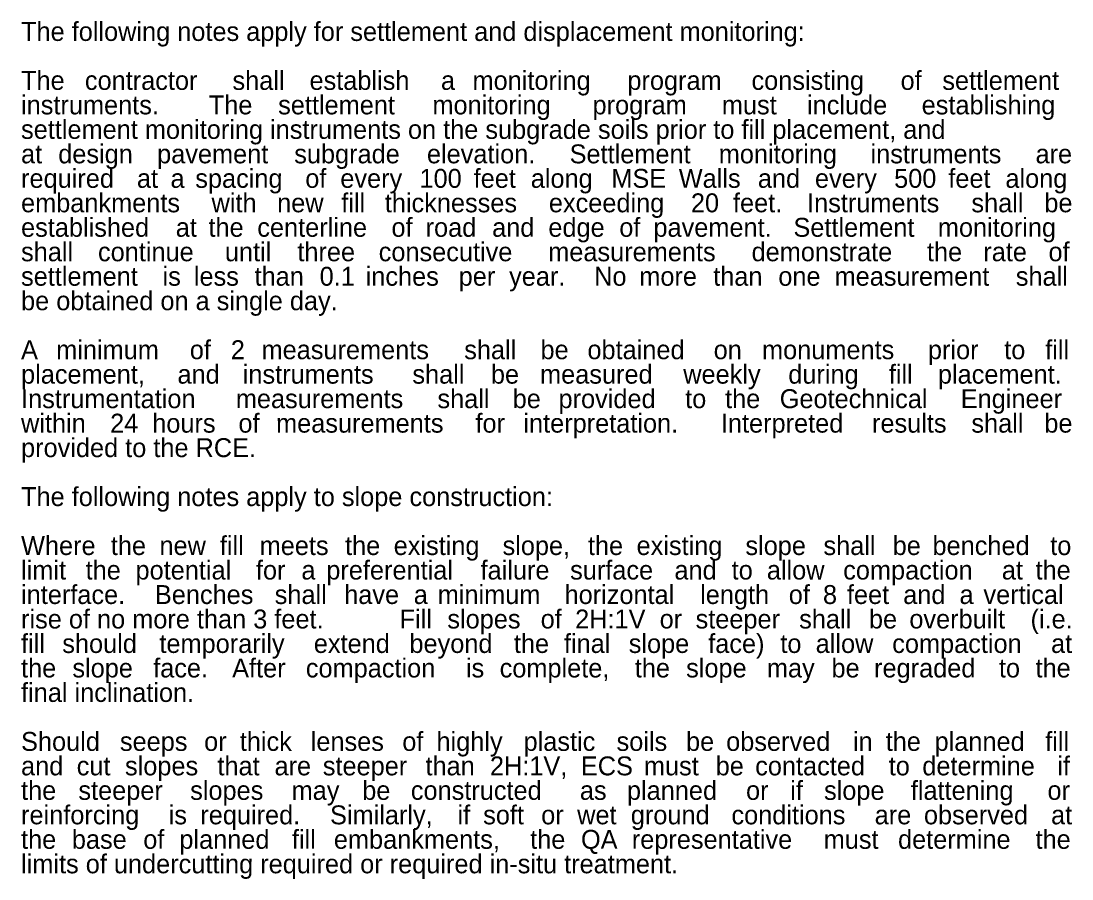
# Model space of a CAD drawing. Extents: x 4804 to 5434, y 4929 to 5221.
# Drawn here: x 5186.9 to 5263.8, y 5038.5 to 5101.3 of the extents above; entities that cross this region are included whole.
import ezdxf

# ---------------------------------------------------------------- set-up
doc = ezdxf.new("R2010")
doc.units = 0
doc.layers.add('RD_TX_RoadID', color=7, linetype='Continuous')

msp = doc.modelspace()

# ---------------------------------------------------------------- texts
at = {"layer": 'RD_TX_RoadID'}
for s, p in [('The following notes apply for settlement and displacement monitoring:', (5186.949, 5099.812)), ('The ', (5186.949, 5096.229)), ('contractor ', (5191.618, 5096.229)), ('shall ', (5202.412, 5096.229)), ('establish ', (5208.048, 5096.229)), ('a ', (5217.661, 5096.229)), ('monitoring ', (5219.967, 5096.229)), ('program ', (5231.297, 5096.229)), ('consisting ', (5240.372, 5096.229)), ('of ', (5251.274, 5096.229)), ('settlement ', (5254.329, 5096.229)), ('instruments. ', (5186.949, 5094.437)), (' The ', (5200.166, 5094.437)), ('settlement ', (5205.753, 5094.437)), ('monitoring ', (5217.036, 5094.437)), ('program ', (5228.747, 5094.437)), ('must ', (5238.203, 5094.437)), ('include ', (5244.435, 5094.437)), ('establishing ', (5252.817, 5094.437)), ('settlement monitoring instruments on the subgrade soils prior to fill placement, and ', (5186.949, 5092.645)), ('at ', (5186.949, 5090.853)), ('design ', (5189.668, 5090.853)), ('pavement ', (5196.901, 5090.853)), ('subgrade ', (5206.929, 5090.853)), ('elevation. ', (5216.635, 5090.853)), (' Settlement ', (5226.555, 5090.853)), ('monitoring ', (5237.978, 5090.853)), ('instruments ', (5249.078, 5090.853)), ('are ', (5261.146, 5090.853)), ('required ', (5186.949, 5089.061)), ('at ', (5195.424, 5089.061)), ('a ', (5197.88, 5089.061)), ('spacing ', (5199.692, 5089.061)), ('of ', (5207.737, 5089.061)), ('every ', (5210.3, 5089.061)), ('100 ', (5216.09, 5089.061)), ('feet ', (5220.053, 5089.061)), ('along ', (5224.228, 5089.061)), ('MSE ', (5230.123, 5089.061)), ('Walls ', (5235.052, 5089.061)), ('and ', (5240.839, 5089.061)), ('every ', (5245.015, 5089.061)), ('500 ', (5250.805, 5089.061)), ('feet ', (5254.768, 5089.061)), ('along ', (5258.943, 5089.061)), ('embankments ', (5186.949, 5087.27)), ('with ', (5200.883, 5087.27)), ('fill ', (5210.369, 5087.27)), ('thicknesses ', (5213.553, 5087.27)), ('exceeding ', (5225.553, 5087.27)), ('20 ', (5235.941, 5087.27)), ('feet. ', (5239.019, 5087.27)), (' Instruments ', (5243.923, 5087.27)), ('shall ', (5256.457, 5087.27)), ('be ', (5261.792, 5087.27)), ('new ', (5205.679, 5087.27)), ('established ', (5186.949, 5085.478)), ('at ', (5198.263, 5085.478)), ('the ', (5200.655, 5085.478)), ('centerline ', (5204.229, 5085.478)), ('of ', (5214.038, 5085.478)), ('road ', (5216.537, 5085.478)), ('and ', (5221.402, 5085.478)), ('edge ', (5225.515, 5085.478)), ('of ', (5230.703, 5085.478)), ('pavement. ', (5233.202, 5085.478)), ('Settlement ', (5243.441, 5085.478)), ('monitoring ', (5254.001, 5085.478)), ('shall ', (5186.949, 5083.686)), ('continue ', (5192.576, 5083.686)), ('until ', (5201.856, 5083.686)), ('three ', (5207.158, 5083.686)), ('consecutive ', (5213.107, 5083.686)), ('measurements ', (5225.506, 5083.686)), ('demonstrate ', (5240.378, 5083.686)), ('the ', (5253.205, 5083.686)), ('rate ', (5257.327, 5083.686)), ('of ', (5262.094, 5083.686)), ('settlement ', (5186.949, 5081.894)), ('is ', (5197.298, 5081.894)), ('less ', (5199.587, 5081.894)), ('than ', (5204.027, 5081.894)), ('0.1 ', (5208.787, 5081.894)), ('inches ', (5212.152, 5081.894)), ('  No ', (5227.835, 5081.894)), ('than ', (5237.573, 5081.894)), ('measurement ', (5246.449, 5081.894)), ('shall ', (5259.703, 5081.894)), ('per ', (5218.956, 5081.894)), ('year. ', (5222.643, 5081.894)), ('more ', (5232.166, 5081.894)), ('one ', (5242.333, 5081.894)), ('be obtained on a single day.  ', (5186.949, 5080.102)), ('A ', (5186.949, 5076.519)), ('minimum ', (5189.519, 5076.519)), ('of ', (5199.291, 5076.519)), ('2 ', (5202.289, 5076.519)), ('measurements ', (5204.538, 5076.519)), ('shall ', (5219.363, 5076.519)), ('be ', (5224.942, 5076.519)), ('obtained ', (5228.373, 5076.519)), ('monuments ', (5241.142, 5076.519)), ('prior ', (5253.277, 5076.519)), ('to ', (5258.856, 5076.519)), ('fill ', (5261.854, 5076.519)), ('on ', (5237.605, 5076.519)), ('placement, ', (5186.949, 5074.727)), ('and ', (5198.389, 5074.727)), ('instruments ', (5203.165, 5074.727)), ('shall ', (5215.57, 5074.727)), ('be ', (5221.314, 5074.727)), ('measured ', (5224.908, 5074.727)), ('weekly ', (5235.382, 5074.727)), ('during ', (5243.062, 5074.727)), ('fill ', (5250.416, 5074.727)), ('placement. ', (5254.007, 5074.727)), ('Instrumentation ', (5186.949, 5072.935)), ('measurements ', (5202.657, 5072.935)), ('shall ', (5217.404, 5072.935)), ('be ', (5222.906, 5072.935)), ('provided ', (5226.258, 5072.935)), ('to ', (5235.521, 5072.935)), ('the ', (5238.441, 5072.935)), ('Geotechnical ', (5242.437, 5072.935)), ('Engineer ', (5255.677, 5072.935)), ('within ', (5186.949, 5071.143)), ('24 ', (5193.465, 5071.143)), ('hours ', (5196.544, 5071.143)), ('of ', (5202.847, 5071.143)), ('measurements ', (5205.601, 5071.143)), ('for ', (5220.182, 5071.143)), ('interpretation. ', (5223.689, 5071.143)), (' Interpreted ', (5237.619, 5071.143)), ('results ', (5249.186, 5071.143)), ('shall ', (5256.456, 5071.143)), ('be ', (5261.792, 5071.143)), ('provided to the RCE.  ', (5186.949, 5069.351)), ('The following notes apply to slope construction:', (5186.949, 5065.768)), ('Where ', (5186.949, 5062.184)), ('the ', (5193.515, 5062.184)), ('new ', (5197.072, 5062.184)), ('fill ', (5201.489, 5062.184)), ('meets ', (5204.4, 5062.184)), ('the ', (5210.645, 5062.184)), ('existing ', (5214.202, 5062.184)), ('slope, ', (5222.165, 5062.184)), ('the ', (5228.409, 5062.184)), ('existing ', (5231.966, 5062.184)), ('slope ', (5239.929, 5062.184)), ('shall ', (5245.636, 5062.184)), ('be ', (5250.699, 5062.184)), ('benched ', (5253.611, 5062.184)), ('to ', (5262.221, 5062.184)), ('limit ', (5186.949, 5060.392)), ('the ', (5191.672, 5060.392)), ('potential ', (5195.321, 5060.392)), ('for ', (5204.127, 5060.392)), ('preferential ', (5209.276, 5060.392)), ('failure ', (5220.556, 5060.392)), ('surface ', (5227.107, 5060.392)), ('and ', (5234.734, 5060.392)), ('to ', (5238.921, 5060.392)), ('allow ', (5241.495, 5060.392)), ('compaction ', (5247.079, 5060.392)), ('at ', (5258.681, 5060.392)), ('the ', (5261.148, 5060.392)), ('a ', (5207.453, 5060.392)), ('interface. ', (5186.949, 5058.6)), (' Benches ', (5196.224, 5058.6)), ('shall ', (5205.501, 5058.6)), ('have ', (5210.585, 5058.6)), ('a ', (5215.67, 5058.6)), ('minimum ', (5217.423, 5058.6)), ('horizontal ', (5226.699, 5058.6)), ('length ', (5236.617, 5058.6)), ('of ', (5243.097, 5058.6)), ('8 ', (5245.6, 5058.6)), ('feet ', (5247.353, 5058.6)), ('and ', (5251.468, 5058.6)), ('a ', (5255.585, 5058.6)), ('vertical ', (5257.338, 5058.6)), ('rise of no more than 3 feet.', (5186.949, 5056.809)), ('Fill ', (5214.639, 5056.809)), ('slopes ', (5218.129, 5056.809)), ('of ', (5224.952, 5056.809)), ('2H:1V ', (5227.474, 5056.809)), ('or ', (5233.653, 5056.809)), ('steeper ', (5236.284, 5056.809)), ('shall ', (5243.86, 5056.809)), ('be ', (5248.963, 5056.809)), ('overbuilt ', (5251.917, 5056.809)), ('(i.e. ', (5260.78, 5056.809)), ('fill ', (5186.949, 5055.017)), ('should ', (5189.965, 5055.017)), ('temporarily ', (5197.067, 5055.017)), ('extend ', (5208.361, 5055.017)), ('beyond ', (5215.355, 5055.017)), ('the ', (5222.995, 5055.017)), ('final ', (5226.657, 5055.017)), ('slope ', (5231.394, 5055.017)), ('face) ', (5237.207, 5055.017)), ('to ', (5242.481, 5055.017)), ('allow ', (5245.068, 5055.017)), ('compaction ', (5250.666, 5055.017)), ('at ', (5262.282, 5055.017)), ('the ', (5186.949, 5053.225)), ('slope ', (5190.705, 5053.225)), ('face. ', (5196.611, 5053.225)), (' After ', (5201.873, 5053.225)), ('compaction ', (5207.777, 5053.225)), ('is ', (5219.487, 5053.225)), ('complete, ', (5221.954, 5053.225)), ('the ', (5231.837, 5053.225)), ('slope ', (5235.592, 5053.225)), ('may ', (5241.499, 5053.225)), ('be ', (5246.224, 5053.225)), ('regraded ', (5249.337, 5053.225)), ('to ', (5258.468, 5053.225)), ('the ', (5261.148, 5053.225)), ('final inclination.', (5186.949, 5051.433)), ('Should ', (5186.949, 5047.849)), ('seeps ', (5194.18, 5047.849)), ('or ', (5200.338, 5047.849)), ('thick ', (5202.947, 5047.849)), ('lenses ', (5208.136, 5047.849)), ('of ', (5214.832, 5047.849)), ('highly ', (5217.333, 5047.849)), ('plastic ', (5223.703, 5047.849)), ('soils ', (5230.504, 5047.849)), ('be ', (5235.586, 5047.849)), ('observed ', (5238.519, 5047.849)), ('in ', (5247.793, 5047.849)), ('the ', (5250.188, 5047.849)), ('planned ', (5253.764, 5047.849)), ('fill ', (5261.854, 5047.849)), ('and ', (5186.949, 5046.058)), ('cut ', (5191.019, 5046.058)), ('slopes ', (5194.551, 5046.058)), ('that ', (5201.309, 5046.058)), ('are ', (5205.485, 5046.058)), ('steeper ', (5209.019, 5046.058)), ('than ', (5216.529, 5046.058)), ('2H:1V, ', (5221.243, 5046.058)), ('ECS ', (5227.893, 5046.058)), ('must ', (5232.502, 5046.058)), ('be ', (5237.754, 5046.058)), ('contacted ', (5240.643, 5046.058)), ('to ', (5250.408, 5046.058)), ('determine ', (5252.865, 5046.058)), ('if ', (5262.739, 5046.058)), ('the ', (5186.949, 5044.266)), ('steeper ', (5191.144, 5044.266)), ('slopes ', (5199.318, 5044.266)), ('be ', (5211.904, 5044.266)), ('constructed ', (5215.456, 5044.266)), ('planned ', (5231.264, 5044.266)), ('if ', (5243.202, 5044.266)), ('slope ', (5245.677, 5044.266)), ('flattening ', (5252.023, 5044.266)), ('may ', (5206.739, 5044.266)), ('as ', (5227.819, 5044.266)), ('or ', (5239.973, 5044.266)), ('or ', (5262.019, 5044.266)), ('reinforcing ', (5186.949, 5042.474)), ('is ', (5197.748, 5042.474)), ('required. ', (5200.059, 5042.474)), (' Similarly, ', (5209.033, 5042.474)), ('if ', (5218.868, 5042.474)), ('soft ', (5220.747, 5042.474)), ('or ', (5224.99, 5042.474)), ('wet ', (5227.623, 5042.474)), ('ground ', (5231.546, 5042.474)), ('conditions ', (5238.906, 5042.474)), ('are ', (5249.382, 5042.474)), ('observed ', (5252.984, 5042.474)), ('at ', (5262.282, 5042.474)), ('the ', (5186.949, 5040.682)), ('base ', (5190.665, 5040.682)), ('of ', (5195.888, 5040.682)), ('planned ', (5198.528, 5040.682)), ('fill ', (5206.758, 5040.682)), ('embankments, ', (5209.828, 5040.682)), ('the ', (5224.187, 5040.682)), ('QA ', (5227.902, 5040.682)), ('representative ', (5231.619, 5040.682)), ('must ', (5245.654, 5040.682)), ('determine ', (5251.09, 5040.682)), ('the ', (5261.148, 5040.682)), ('limits of undercutting required or required in-situ treatment.', (5186.949, 5038.89))]:
    msp.add_text(s, height=1.3845, dxfattribs=at).set_placement(p)

doc.saveas('drawing.dxf')
